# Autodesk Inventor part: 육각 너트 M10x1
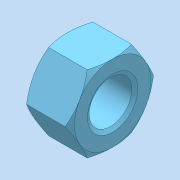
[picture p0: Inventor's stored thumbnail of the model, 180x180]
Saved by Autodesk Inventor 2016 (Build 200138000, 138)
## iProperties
Created: 2024-08
Part Number: 육각 너트 M10x1
Material: 일반
Description: 6각 너트 및 6각 가는 너트
Document SubType Name: Modeling
Designer: pc-7
Density: 1 g/cm^3
Appearance: 기본값
Author: jhkim
Sending System: Autodesk Inventor 2025
Preprocessor: ST-DEVELOPER v20
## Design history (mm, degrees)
node "육각 너트 M10x11"
node "솔리드1"
body "Solid1"
